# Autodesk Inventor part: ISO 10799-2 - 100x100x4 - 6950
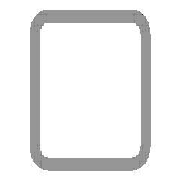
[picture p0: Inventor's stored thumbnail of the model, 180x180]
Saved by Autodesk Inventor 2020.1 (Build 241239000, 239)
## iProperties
Created: 2019-10
Part Number: ISO 10799-2 - 100x100x4 - 6950
Material: Stainless Steel
Description: Structural steels - Cold-formed, welded, structural hollow sections
Document SubType Name: Modeling
Standard: ISO
Designer: Synergysoft Dell02
Standard Revision: First edition 2011-09-15
Standards Organization: ISO
Language: en-US
Size Designation: 100x100x4
Categories: <MemberInstance><Categories><Category DisplayName="Structural Shapes" InternalName="089c4875-fa83-4c05-b084-43b9cc11f5ed" Mnemonic="GRDR"><CategoryParameter Dis
Stock Number: 100x100x4
Density: 8 g/cm^3
Appearance: Semi-Polished
_CCFamilyMember: 43
_CCFamilyDisplayName: ISO 10799-2 (Square) - Structural steels - Cold-formed, welded, structural hollow sections
_FrameMemberDoc: Frame Member File
_Version: 15.0.0
_GetPNFromCC: 1
G_L: 6950.000 mm
G_W: 100.000 mm
G_H: 100.000 mm
+4DB5E8CF-B8CC-4BE0-A447-7D2CE2D894C6+CUTDETAIL1: Cut Angle 90.00 deg
IsCustomPart: 1
Author: Synergysoft Dell02
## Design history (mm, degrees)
node "Start Plane"
node "End Plane"
sketch "Sketch"
  geometry: L1 (-50, -42)-(-50, 42); L2 (-42, 50)-(42, 50); L3 (50, 42)-(50, -42); L4 (42, -50)-(-42, -50); L5 (-42, 46)-(42, 46); L6 (46, 42)-(46, -42); L7 (42, -46)-(-42, -46); L8 (-46, -42)-(-46, 42); L9 (0, 72.32)-(0, -72.32) reference; L10 (-72.32, 0)-(72.32, 0) reference; A1 r 8 centre (-42, -42) between (-50, -42) and (-42, -50); A2 r 8 centre (42, 42) between (50, 42) and (42, 50); A3 r 8 centre (-42, 42) between (-42, 50) and (-50, 42); A4 r 8 centre (42, -42) between (42, -50) and (50, -42); A5 r 4 centre (-42, 42) between (-42, 46) and (-46, 42); A6 r 4 centre (42, 42) between (46, 42) and (42, 46); A7 r 4 centre (42, -42) between (42, -46) and (46, -42); A8 r 4 centre (-42, -42) between (-46, -42) and (-42, -46)
  constraints: 16 end point, 16 point on circle, 8 centre point, 8 tangent, 4 parallel, 3 equal radius, 2 perpendicular, 7 other
  dimensions: "d7" = 8 radius of A1 (= G_IR); "d9" = 100 distance between parallel lines of L1 L3 (= G_W); "d11" = 100 distance between parallel lines of L2 L4 (= G_H); "d12" = 4 distance between parallel lines of L3 L6 (= G_T); "d15" = 50 distance between parallel lines of L9 L3 (= 0.5 x d9); "d16" = 50 distance between parallel lines of L2 L10 (= 0.5 x d11)
extrude "Body" new body sketch "Sketch" stored distance "d3" = 6950 (= G_L); taper "d4" = 0 deg
node "Driven Length"
  sketch "Sketch3"
    geometry: L1 (0, 0)-(10, 0) reference
    constraints: 2 end point, 1 horizontal
  workplane "Work Plane3"
  sketch "Sketch4"
    geometry: L1 (-2, 50)-(12, 50) reference; L2 (-2, 7000)-(12, 7000) reference
    dimensions: "d18" = 6950 distance between parallel lines of L1 L2 (derived)
workplane "Work Plane4"
split "Split1"
body "Solid1"
other parameters: "G_W" = 100 [user parameter; used in 1 equation term], "G_H" = 100 [user parameter; used in 1 equation term], "G_T" = 4 [user parameter; used in 1 equation term], "G_IR" = 8 [user parameter; used in 1 equation term], "G_L" = 6950 (= d18) [user parameter; used in 1 equation term], "G_OFFSET_END" = 0 [user parameter; used in 1 equation term], "d17" = 90 deg, "MAS" = 1.17 [user parameter]
